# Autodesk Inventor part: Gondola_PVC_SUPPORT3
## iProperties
Shininess: 64.0
Length Units: 11272
Angle Units: 11279
Time Units: 11290
Mass Units: 11286
Length Display Precision: 3
Angle Display Precision: 2
Compacted: True
Part Number: Gondola_PVC_SUPPORT3
Document SubType Name: Modeling
Created: 2004-08
Designer: John Blackburn
Manufacturer: Standard
Standards Organization: Custom
Material: PVC-Piping
Density: 0.0
Volumn: 0.0
Area: 0.0
PropertySet Name: Model Information
Control State: 0
Master: False
Checked Out: False
Author: John Blackburn
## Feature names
1. Base1
